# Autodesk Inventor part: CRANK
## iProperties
Shininess: 64.0
Length Units: 11269
Angle Units: 11279
Time Units: 11290
Mass Units: 11283
Length Display Precision: 3
Angle Display Precision: 2
Compacted: True
Part Number: CRANK
Document SubType Name: Modeling
Created: 2004-05
Designer: Daniel
Manufacturer: Standard
Standards Organization: Custom
Density: 0.0
Volumn: 0.0
Area: 0.0
PropertySet Name: Model Information
Control State: 0
Master: False
Checked Out: False
Author: Daniel
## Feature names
1. Extrusion1
2. Extrusion2
3. Extrusion3
4. Extrusion4
5. Extrusion5
6. Extrusion6
7. Extrusion7
8. Extrusion8
